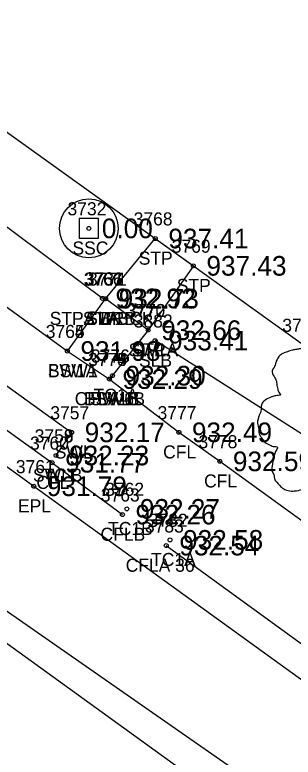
# Model space of a CAD drawing. Extents: x 1575382 to 1578175, y 1099175 to 1101955.
# Drawn here: x 1577449.6 to 1577470.9, y 1100893.8 to 1100950.6 of the extents above; entities that cross this region are included whole.
import ezdxf

# ---------------------------------------------------------------- set-up
doc = ezdxf.new("R2010")
doc.units = 0
for name, color, linetype in [('RD_EX_Bldg', 7, 'Continuous'), ('RD_EX_Bldg_txCode', 7, 'Continuous'), ('RD_EX_Conc', 7, 'Continuous'), ('RD_EX_Conc_txCode', 7, 'Continuous'), ('RD_EX_Road', 7, 'Continuous'), ('RD_EX_Road_txCode', 7, 'Continuous'), ('RD_EX_TX_Conc_ELEV', 7, 'Continuous'), ('RD_EX_TX_Road_ELEV', 7, 'Continuous'), ('RD_EX_TX_UT_ELEV', 7, 'Continuous'), ('RD_EX_TX_VEG_ELEV', 7, 'Continuous'), ('RD_EX_UT', 7, 'Continuous'), ('RD_EX_UT_txCode', 7, 'Continuous'), ('RD_EX_VEG', 7, 'Continuous'), ('RD_EX_VEG_txCode', 7, 'Continuous'), ('RD_HC_Cl', 7, 'Continuous'), ('RD_SMD_Locator', 7, 'Continuous')]:
    doc.layers.add(name, color=color, linetype=linetype)

msp = doc.modelspace()

# ---------------------------------------------------------------- linework, layer by layer
at = {"layer": 'RD_EX_Bldg'}
msp.add_lwpolyline([(1577366.782, 1101000.49), (1577471.682, 1100925.355), (1577510.624, 1100979.985), (1577405.723, 1101055.12), (1577366.782, 1101000.49)], dxfattribs=at)
at = {"layer": 'RD_EX_Conc'}
for p, q in [((1577453.601, 1100924.886), (1577456.526, 1100928.882)), ((1577459.785, 1100926.48), (1577456.819, 1100922.745))]:
    msp.add_line(p, q, dxfattribs=at)
for points in [[(1577260.091, 1101055.735), (1577271.299, 1101047.569), (1577312.394, 1101017.332), (1577352.653, 1100988.383), (1577392.281, 1100959.713), (1577433.556, 1100929.93), (1577452.436, 1100916.348), (1577457.816, 1100912.386)], [(1577352.786, 1100991.572), (1577355.363, 1100995.858), (1577382.695, 1100975.989), (1577386.313, 1100973.352), (1577395.614, 1100966.73), (1577398.827, 1100964.395), (1577422.404, 1100947.354), (1577425.708, 1100945.102), (1577453.601, 1100924.886), (1577456.819, 1100922.745)], [(1577352.786, 1100991.572), (1577393.938, 1100961.919), (1577435.198, 1100932.141), (1577453.925, 1100918.672), (1577452.73, 1100916.903)], [(1577456.526, 1100928.882), (1577460.332, 1100933.485), (1577463.245, 1100931.398), (1577459.785, 1100926.48), (1577456.526, 1100928.882)], [(1577456.819, 1100922.745), (1577462.137, 1100918.675), (1577465.272, 1100916.457), (1577478.599, 1100906.843)], [(1577461.17, 1100910.016), (1577474.589, 1100900.285), (1577474.589, 1100900.285), (1577481.643, 1100896.579), (1577490.243, 1100895.495), (1577497.868, 1100899.643), (1577502.565, 1100908.212), (1577505.115, 1100915.094)]]:
    msp.add_lwpolyline(points, dxfattribs=at)
at = {"layer": 'RD_EX_Road'}
msp.add_lwpolyline([(1577251.257, 1101061.341), (1577255.442, 1101056.285), (1577270.08, 1101045.564), (1577310.681, 1101015.777), (1577351.283, 1100986.437), (1577391.252, 1100957.766), (1577432.133, 1100928.26), (1577451.028, 1100914.552), (1577473.397, 1100898.426), (1577474.178, 1100899.605), (1577481.335, 1100895.669), (1577490.142, 1100894.697), (1577498.51, 1100899.091), (1577503.297, 1100907.838), (1577513.461, 1100934.773)], dxfattribs=at)
at = {"layer": 'RD_EX_UT'}
for p, q in [((1577455.993, 1100935.009), (1577454.493, 1100935.009)), ((1577454.493, 1100935.009), (1577454.493, 1100933.509)), ((1577455.993, 1100933.509), (1577455.993, 1100935.009)), ((1577454.493, 1100933.509), (1577455.993, 1100933.509))]:
    msp.add_line(p, q, dxfattribs=at)
msp.add_lwpolyline([(1577649.032, 1100804.001), (1577493.924, 1100873.726), (1577386.899, 1100948.146)], dxfattribs=at)
msp.add_circle((1577455.243, 1100934.259), 2.25, dxfattribs=at)
at = {"layer": 'RD_EX_VEG'}
msp.add_line((1577456.285, 1100928.906), (1577428.995, 1100949.196), dxfattribs=at)
msp.add_lwpolyline([(1577490.523, 1100943.069), (1577476.131, 1100915.618), (1577460.315, 1100925.68)], dxfattribs=at)
msp.add_spline([(1577475.224, 1100926.659), (1577474.925, 1100926.684), (1577474.6, 1100926.584), (1577474.35, 1100926.484), (1577474.125, 1100926.409), (1577473.9, 1100926.309), (1577473.6, 1100926.134), (1577473.375, 1100925.934), (1577473.25, 1100925.684), (1577473.2, 1100925.46), (1577473.15, 1100925.185), (1577473.15, 1100925.01), (1577473.025, 1100924.985), (1577472.875, 1100925.01), (1577472.626, 1100925.085), (1577472.376, 1100925.085), (1577472.126, 1100925.085), (1577471.776, 1100925.06), (1577471.426, 1100925.06), (1577471.151, 1100925.01), (1577470.826, 1100924.96), (1577470.452, 1100924.835), (1577470.102, 1100924.71), (1577469.802, 1100924.46), (1577469.552, 1100923.985), (1577469.427, 1100923.635), (1577469.277, 1100923.385), (1577469.427, 1100922.936), (1577469.602, 1100922.586), (1577469.627, 1100922.386), (1577469.702, 1100921.961), (1577469.802, 1100921.736), (1577469.927, 1100921.536), (1577469.852, 1100921.511), (1577469.477, 1100921.461), (1577469.177, 1100921.361), (1577468.752, 1100921.136), (1577468.527, 1100920.912), (1577468.427, 1100920.587), (1577468.402, 1100920.237), (1577468.303, 1100920.037), (1577468.228, 1100919.762), (1577468.203, 1100919.687), (1577468.153, 1100919.362), (1577468.253, 1100918.912), (1577468.278, 1100918.563), (1577468.402, 1100918.338), (1577468.552, 1100918.163), (1577468.727, 1100917.913), (1577469.127, 1100917.688), (1577469.452, 1100917.588), (1577469.652, 1100917.563), (1577469.477, 1100917.063), (1577469.427, 1100916.713), (1577469.302, 1100916.314), (1577469.302, 1100916.239), (1577469.252, 1100915.764), (1577469.402, 1100915.439), (1577469.477, 1100915.064), (1577469.652, 1100914.839), (1577469.927, 1100914.539), (1577470.252, 1100914.314), (1577470.751, 1100914.189), (1577471.151, 1100914.214), (1577471.726, 1100914.389), (1577471.976, 1100914.464), (1577471.951, 1100914.289), (1577471.976, 1100913.915), (1577471.976, 1100913.49), (1577472.126, 1100913.165), (1577472.226, 1100912.89), (1577472.376, 1100912.64), (1577472.701, 1100912.415), (1577473.1, 1100912.34), (1577473.525, 1100912.19), (1577473.975, 1100912.115), (1577474.475, 1100912.09), (1577475.075, 1100912.24), (1577475.349, 1100912.365), (1577475.449, 1100912.54), (1577475.649, 1100912.915), (1577475.599, 1100913.14), (1577475.624, 1100913.74), (1577475.724, 1100913.565), (1577475.899, 1100913.215), (1577476.399, 1100912.915), (1577476.799, 1100912.74), (1577477.274, 1100912.59), (1577477.573, 1100912.515), (1577478.048, 1100912.59), (1577478.423, 1100912.665), (1577478.798, 1100912.79), (1577479.098, 1100913.065), (1577479.273, 1100913.34), (1577479.323, 1100913.615), (1577479.398, 1100913.99), (1577479.448, 1100914.164)], degree=3, dxfattribs=at)
at = {"layer": 'RD_HC_Cl'}
msp.add_line((1577222.651, 1101065.297), (1577474.471, 1100884.196), dxfattribs=at)
at = {"layer": 'RD_SMD_Locator'}
for centre in [(1577455.243, 1100934.259), (1577460.332, 1100933.485), (1577463.245, 1100931.398), (1577456.285, 1100928.906), (1577456.526, 1100928.882), (1577456.526, 1100928.882), (1577456.526, 1100928.882), (1577459.785, 1100926.48), (1577459.785, 1100926.48), (1577460.315, 1100925.68), (1577453.601, 1100924.886), (1577453.601, 1100924.886), (1577457.055, 1100923.006), (1577456.819, 1100922.745), (1577456.819, 1100922.745), (1577456.819, 1100922.745), (1577453.925, 1100918.672), (1577462.137, 1100918.675), (1577452.73, 1100916.903), (1577452.73, 1100916.903), (1577452.436, 1100916.348), (1577465.272, 1100916.457), (1577451.028, 1100914.552), (1577458.152, 1100912.823), (1577457.816, 1100912.386), (1577461.46, 1100910.454), (1577461.17, 1100910.016)]:
    msp.add_circle(centre, 0.15, dxfattribs=at)

# ---------------------------------------------------------------- texts
at = {"layer": 'RD_EX_Bldg_txCode'}
msp.add_text('3727', height=1, dxfattribs=at).set_placement((1577470.052, 1100926.355))
at = {"layer": 'RD_EX_Conc_txCode'}
for s, p in [('3768', (1577458.679, 1100934.485)), ('3769', (1577461.591, 1100932.398)), ('STP', (1577459.064, 1100931.485)), ('3766', (1577454.849, 1100929.882)), ('3767', (1577454.872, 1100929.882)), ('3771', (1577455.179, 1100929.882)), ('STP', (1577461.977, 1100929.398)), ('3770', (1577458.116, 1100927.48)), ('3772', (1577458.155, 1100927.48)), ('STPA BRICK', (1577452.25, 1100926.882)), ('STPB', (1577454.786, 1100926.882)), ('SW1B', (1577455.045, 1100926.882)), ('3764', (1577451.947, 1100925.886)), ('3765', (1577451.947, 1100925.886)), ('SW1A', (1577458.289, 1100924.48)), ('STP', (1577458.518, 1100924.48)), ('3773', (1577455.189, 1100923.745)), ('3774', (1577455.189, 1100923.745)), ('3775', (1577455.189, 1100923.745)), ('3776', (1577455.402, 1100924.006)), ('SW1A', (1577452.104, 1100922.886)), ('BSW1', (1577452.12, 1100922.886)), ('TC1A', (1577455.606, 1100921.006)), ('CFLA 6', (1577454.166, 1100920.745)), ('BSW1B', (1577454.867, 1100920.745)), ('SW1B', (1577455.339, 1100920.745)), ('3757', (1577452.295, 1100919.672)), ('3777', (1577460.507, 1100919.675)), ('3758', (1577451.1, 1100917.903)), ('3759', (1577451.1, 1100917.903)), ('3760', (1577450.743, 1100917.348)), ('3778', (1577463.642, 1100917.457)), ('SWL', (1577452.633, 1100916.672)), ('CFL', (1577460.932, 1100916.675)), ('SWLB', (1577450.966, 1100914.903)), ('TC1', (1577451.769, 1100914.903)), ('CFL', (1577451.231, 1100914.348)), ('CFL', (1577464.068, 1100914.457)), ('3762', (1577456.498, 1100913.823)), ('3763', (1577456.162, 1100913.386)), ('3782', (1577459.83, 1100911.454)), ('TC1B', (1577456.719, 1100910.823)), ('3783', (1577459.54, 1100911.016)), ('CFLB', (1577456.139, 1100910.386)), ('TC1A', (1577460.011, 1100908.454)), ('CFLA 36', (1577458.067, 1100908.016))]:
    msp.add_text(s, height=1, dxfattribs=at).set_placement(p)
at = {"layer": 'RD_EX_Road_txCode'}
for s, p in [('3761', (1577449.658, 1100915.552)), ('EPL', (1577449.823, 1100912.552))]:
    msp.add_text(s, height=1, dxfattribs=at).set_placement(p)
at = {"layer": 'RD_EX_TX_Conc_ELEV'}
for s, p in [('937.41', (1577461.332, 1100932.735)), ('937.43', (1577464.245, 1100930.648)), ('932.73', (1577457.526, 1100928.132)), ('932.73', (1577457.526, 1100928.132)), ('932.73', (1577457.526, 1100928.132)), ('932.66', (1577460.785, 1100925.73)), ('932.66', (1577460.785, 1100925.73)), ('931.98', (1577454.601, 1100924.136)), ('931.98', (1577454.601, 1100924.136)), ('932.30', (1577458.055, 1100922.256)), ('932.29', (1577457.819, 1100921.995)), ('932.29', (1577457.819, 1100921.995)), ('932.29', (1577457.819, 1100921.995)), ('932.17', (1577454.925, 1100917.922)), ('932.49', (1577463.137, 1100917.925)), ('932.23', (1577453.73, 1100916.153)), ('932.23', (1577453.73, 1100916.153)), ('931.77', (1577453.436, 1100915.598)), ('932.59', (1577466.272, 1100915.707)), ('932.27', (1577459.152, 1100912.073)), ('932.26', (1577458.816, 1100911.636)), ('932.58', (1577462.46, 1100909.704)), ('932.54', (1577462.17, 1100909.266))]:
    msp.add_text(s, height=1.5, dxfattribs=at).set_placement(p)
at = {"layer": 'RD_EX_TX_Road_ELEV'}
msp.add_text('931.79', height=1.5, dxfattribs=at).set_placement((1577452.028, 1100913.802))
at = {"layer": 'RD_EX_TX_UT_ELEV'}
msp.add_text('0.00', height=1.5, dxfattribs=at).set_placement((1577456.243, 1100933.509))
at = {"layer": 'RD_EX_TX_VEG_ELEV'}
for s, p in [('932.92', (1577457.285, 1100928.156)), ('933.41', (1577461.315, 1100924.93))]:
    msp.add_text(s, height=1.5, dxfattribs=at).set_placement(p)
at = {"layer": 'RD_EX_UT_txCode'}
for s, p in [('3732', (1577453.613, 1100935.259)), ('SSC', (1577453.991, 1100932.259))]:
    msp.add_text(s, height=1, dxfattribs=at).set_placement(p)
at = {"layer": 'RD_EX_VEG_txCode'}
for s, p in [('3731', (1577454.938, 1100929.906)), ('SLA', (1577455.041, 1100926.906)), ('3882', (1577458.685, 1100926.68)), ('SLB', (1577459.086, 1100923.68))]:
    msp.add_text(s, height=1, dxfattribs=at).set_placement(p)

doc.saveas('drawing.dxf')
